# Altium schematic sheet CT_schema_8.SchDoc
size 274 x 160 mm
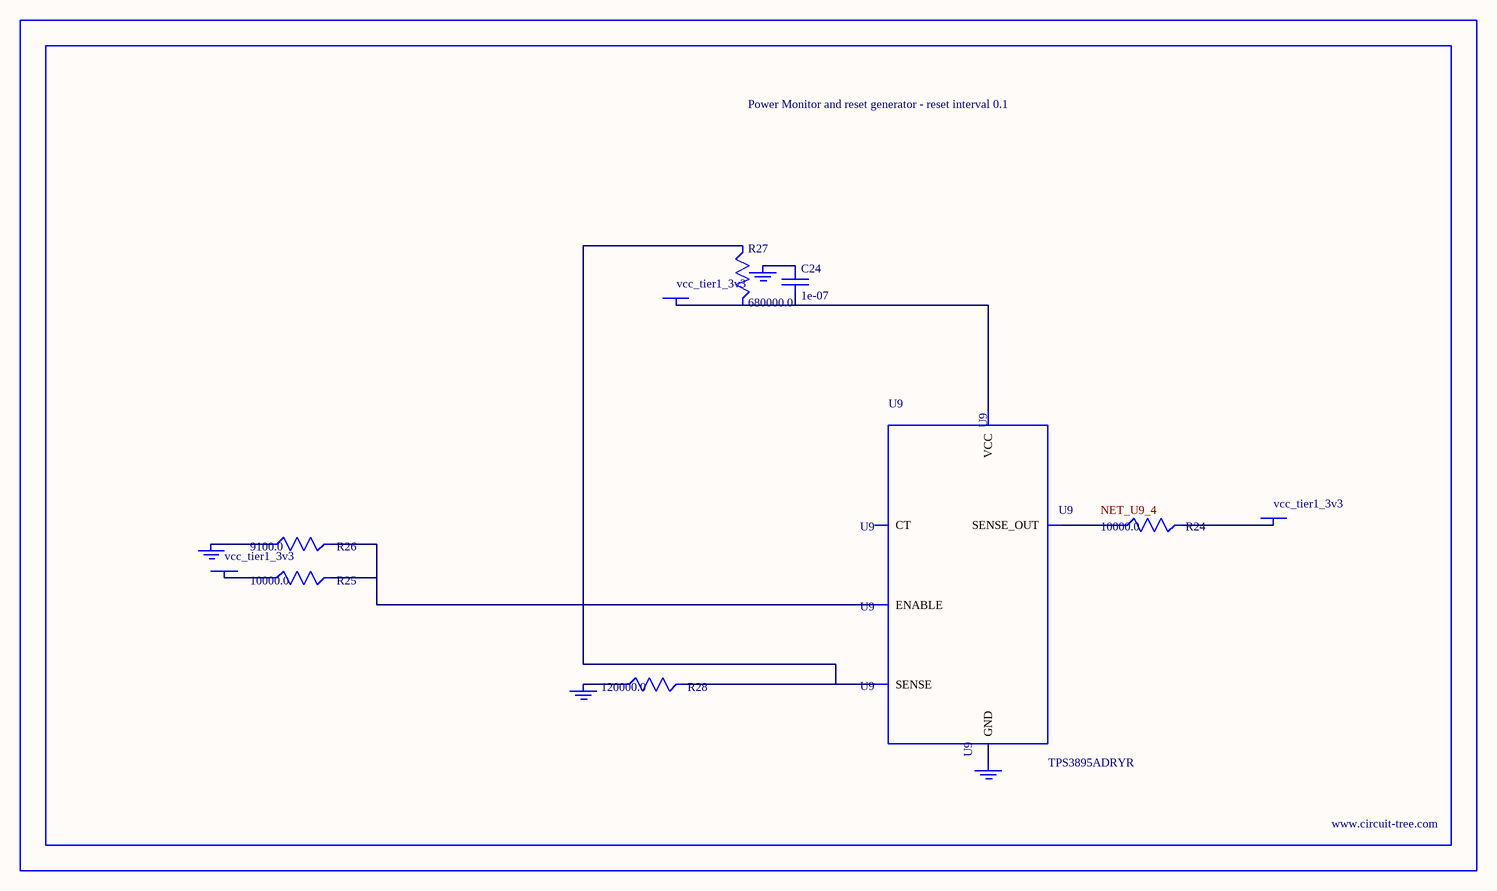
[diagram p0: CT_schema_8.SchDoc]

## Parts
BORDER7  (no value)
C24  1e-07  [C0402]
GND_INSTANCE_7_0  (no value)
GND_INSTANCE_7_1  (no value)
GND_INSTANCE_7_2  (no value)
GND_INSTANCE_7_3  (no value)
POWER_INSTANCE_7_0  vcc_tier1_3v3
POWER_INSTANCE_7_1  vcc_tier1_3v3
POWER_INSTANCE_7_2  vcc_tier1_3v3
R24  10000.0  [R0603]
R25  10000.0  [R0603]
R26  9100.0  [R0603]
R27  680000.0  [R0603]
R28  120000.0  [R0603]
U9  TPS3895ADRYR  [SON-6]

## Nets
NetC24_1: C24.1 GND_INSTANCE_7_2.0(GND)
NetC24_2: C24.2 POWER_INSTANCE_7_2.0(PWR) R27.2 U9.6(VCC)
NetGND_INSTANCE_7_0_0: GND_INSTANCE_7_0.0(GND) R26.1
NetGND_INSTANCE_7_1_0: GND_INSTANCE_7_1.0(GND) R28.1
NetGND_INSTANCE_7_3_0: GND_INSTANCE_7_3.0(GND) U9.2(GND)
NetPOWER_INSTANCE_7_0_0: POWER_INSTANCE_7_0.0(PWR) R25.1
NetPOWER_INSTANCE_7_1_0: POWER_INSTANCE_7_1.0(PWR) R24.2
NetR24_1: R24.1 U9.4(SENSE_OUT)
NetR25_2: R25.2 R26.2 U9.1(ENABLE)
NetR27_1: R27.1 R28.2 U9.3(SENSE)

Not connected (* = marked no-connect by the designer): U9 5(CT)

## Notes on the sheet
- Labels drawn without touching a wire or pin: NET_U9_4

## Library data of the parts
BORDER7 = BORDER_PAGE7
C24 = C0402C104K3RACTU
GND_INSTANCE_7_0-GND_INSTANCE_7_3 = GND
POWER_INSTANCE_7_0-POWER_INSTANCE_7_2 = PWR
R24 R25 = RC0603JR-0710KL
R26 = RC0603JR-079K1L
R27 = RC0603JR-07680KL
R28 = RC0603JR-07120KL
